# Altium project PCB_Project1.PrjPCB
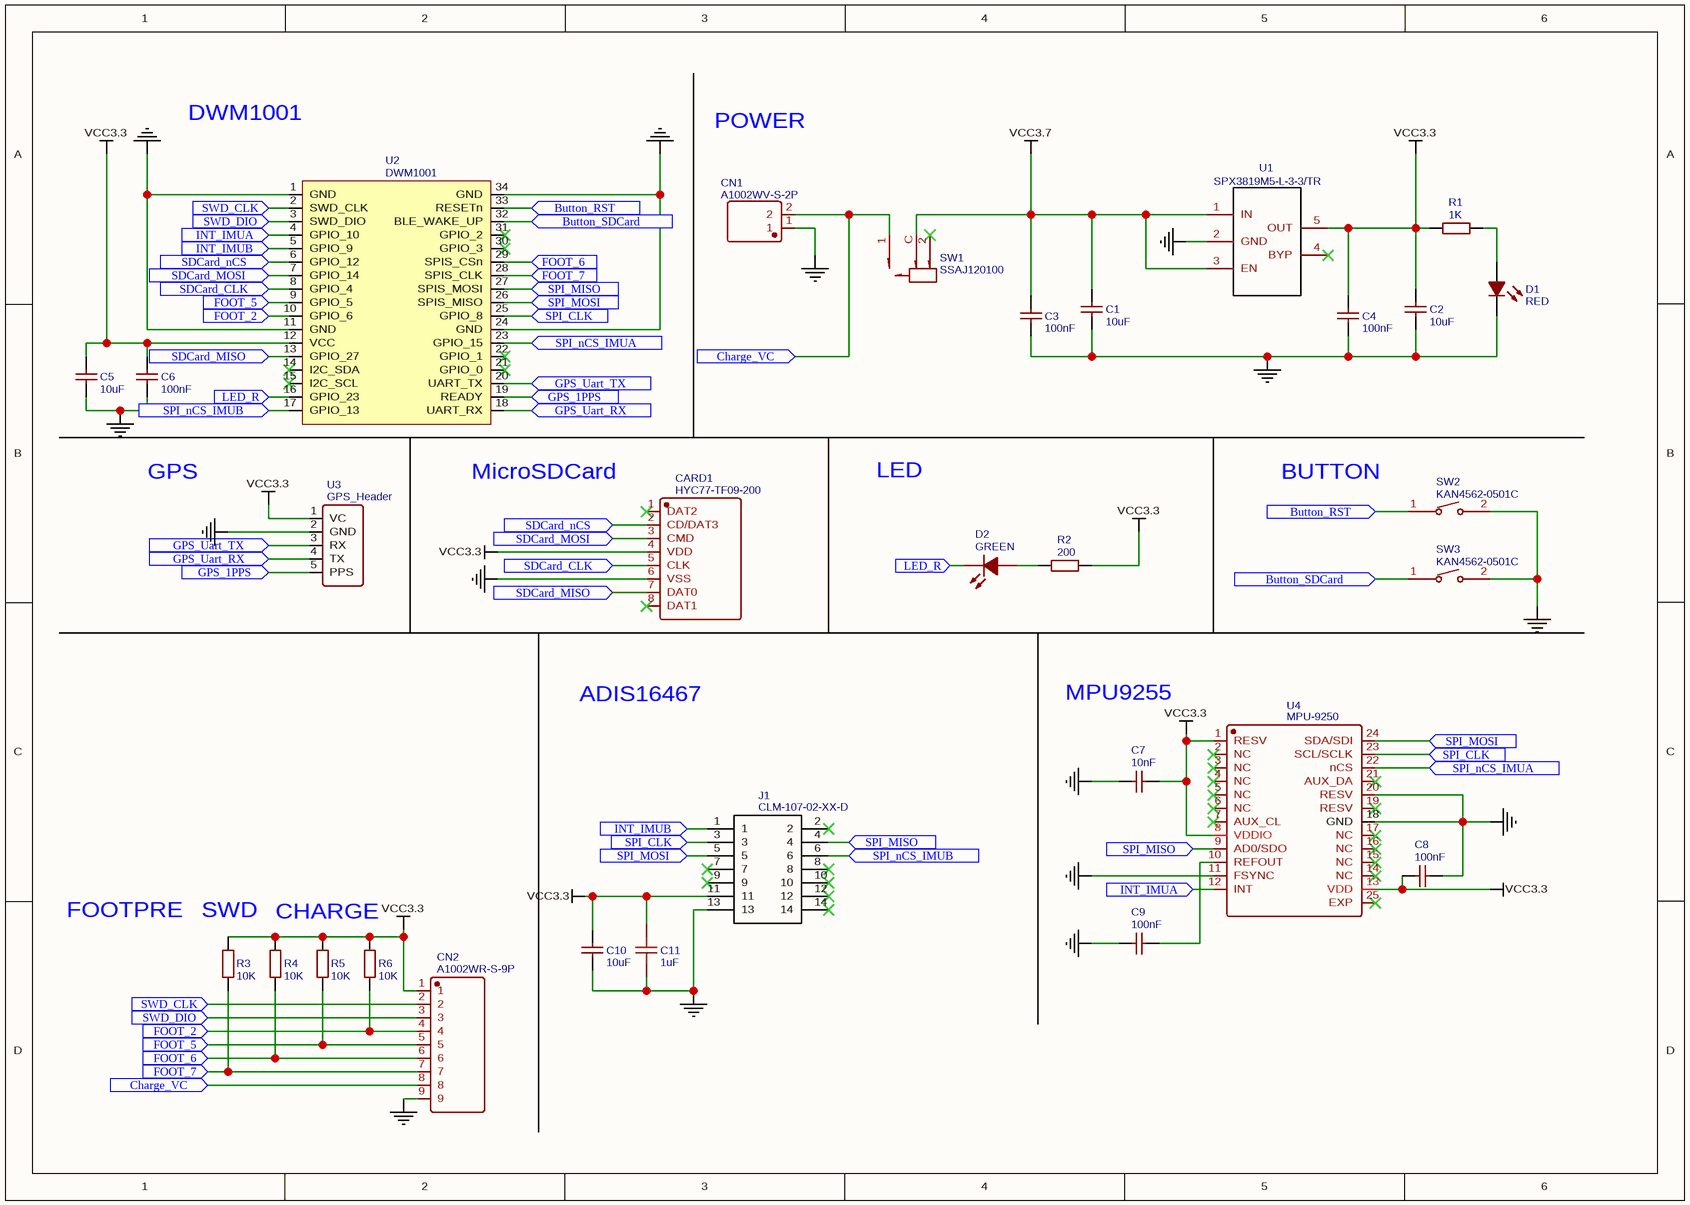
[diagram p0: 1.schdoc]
1 sheet, 30 parts. Net scope: flat (ports and power ports of the same name join across sheets).
Board file: 1.pcbdoc

## Sheet 1.schdoc
size 316 x 224 mm

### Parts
C1  10uF  [0402]
C2  10uF  [0402]
C3  100nF  [0402]
C4  100nF  [0402]
C5  10uF  [0402]
C6  100nF  [0402]
C7  10nF  [0402]
C8  100nF  [0402]
C9  100nF  [0402]
C10  10uF  [0402]
C11  1uF  [0402]
CARD1  HYC77-TF09-200  [TF-015]
CN1  A1002WV-S-2P  [A1002WR-S-2P_LEO]
CN2  A1002WR-S-9P  [A1002WR-S-9P_LEO]
D1  RED  [LED-0603]
D2  GREEN  [LED-0603]
J1  CLM-107-02-XX-D  [*CLM-107-02-XX-D_2]
R1  1K  [0402]
R2  200  [0402]
R3  10K  [0402]
R4  10K  [0402]
R5  10K  [0402]
R6  10K  [0402]
SW1  SSAJ120100  [SW-SMD-5.5X2.5]
SW2  KAN4562-0501C  [KAN4562-0501C]
SW3  KAN4562-0501C  [KAN4562-0501C]
U1  SPX3819M5-L-3-3/TR  [SOT-23-5]
U2  DWM1001  [DWM1001]
U3  GPS_Header  [GPS_HEADER_SMT_NEW]
U4  MPU-9250  [QFN-24-1EP_3X3MM_PITCH0.4MM]

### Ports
Button_RST, Button_SDCard, Charge_VC, FOOT_2, FOOT_5, FOOT_6, FOOT_7, GPS_1PPS, GPS_Uart_RX, GPS_Uart_TX, INT_IMUA, INT_IMUB, LED_R, SDCard_CLK, SDCard_MISO, SDCard_MOSI, SDCard_nCS, SPI_CLK, SPI_MISO, SPI_MOSI, SPI_nCS_IMUA, SPI_nCS_IMUB, SWD_CLK, SWD_DIO

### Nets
GND: C1.1 C2.1 C3.1 C4.1 C5.1 C6.1 C7.1 C8.1 C9.2 C10.1 CARD1.6(VSS) CN1.1 CN2.9 D1.2(C) J1.6 J1.13 SW2.2 SW3.2 U1.2(GND) U2.1(GND) U2.11(GND) U2.17(GPIO_13) U2.24(GND) U2.34(GND) U3.2(GND) U4.11(FSYNC) U4.18(GND) U4.20(RESV) ; port SPI_nCS_IMUB
VCC3.3: C2.2 C4.2 C5.2 C6.2 C7.2 C8.2 C10.2 CARD1.4(VDD) CN2.1 J1.11 R1.1 R2.2 R3.2 R4.2 R5.2 R6.2 U1.5(OUT) U2.12(VCC) U3.1(VC) U4.1(RESV) U4.8(VDDIO) U4.13(VDD)
VCC3.7: C1.2 C3.2 SW1.C U1.1(IN) U1.3(EN)
NetC9_1: C9.1 U4.10(REFOUT)
NetCARD1_2: CARD1.2(CD/DAT3) U2.6(GPIO_12) ; port SDCard_nCS
NetCARD1_3: CARD1.3(CMD) U2.7(GPIO_14) ; port SDCard_MOSI
NetCARD1_5: CARD1.5(CLK) U2.8(GPIO_4) ; port SDCard_CLK
NetCARD1_7: CARD1.7(DAT0) U2.13(GPIO_27) ; port SDCard_MISO
NetCN1_2: CN1.2 CN2.8 SW1.1 ; port Charge_VC
NetCN2_2: CN2.2 CN2.4 CN2.6 R4.1 R6.1 U2.2(SWD_CLK) U2.10(GPIO_6) U2.29(SPIS_CSn) ; port SWD_CLK, port FOOT_2, port FOOT_6
NetCN2_3: CN2.3 CN2.5 CN2.7 R3.1 R5.1 U2.3(SWD_DIO) U2.9(GPIO_5) U2.28(SPIS_CLK) ; port SWD_DIO, port FOOT_5, port FOOT_7
NetD1_1: D1.1(A) R1.2
NetD2_1: D2.1(A) R2.1
NetD2_2: D2.2(K) U2.16(GPIO_23) ; port LED_R
NetJ1_1: J1.1 U2.5(GPIO_9) ; port INT_IMUB
NetJ1_3: J1.3 U2.25(GPIO_8) U4.23(SCL/SCLK) ; port SPI_CLK
NetJ1_4: J1.4 U2.27(SPIS_MOSI) U4.9(AD0/SDO) ; port SPI_MISO
NetJ1_5: J1.5 U2.26(SPIS_MISO) U4.24(SDA/SDI) ; port SPI_MOSI
NetSW2_1: SW2.1 U2.33(RESETn) ; port Button_RST
NetSW3_1: SW3.1 U2.32(BLE_WAKE_UP) ; port Button_SDCard
NetU2_4: U2.4(GPIO_10) U4.12(INT) ; port INT_IMUA
NetU2_18: U2.18(UART_RX) U3.4(TX) ; port GPS_Uart_RX
NetU2_19: U2.19(READY) U3.5(PPS) ; port GPS_1PPS
NetU2_20: U2.20(UART_TX) U3.3(RX) ; port GPS_Uart_TX
NetU2_23: U2.23(GPIO_15) U4.22(nCS) ; port SPI_nCS_IMUA

Not connected (* = marked no-connect by the designer): C11 1 2; CARD1 1(DAT2)* 8(DAT1)*; J1 2* 7* 8* 9* 10* 12* 14*; SW1 2*; U1 4(BYP)*; U2 14(I2C_SDA)* 15(I2C_SCL)* 21(GPIO_0)* 22(GPIO_1)* 30(GPIO_3)* 31(GPIO_2)*; U4 2(NC)* 3(NC)* 4(NC)* 5(NC)* 6(NC)* 7(AUX_CL)* 14(NC)* 15(NC)* 16(NC)* 17(NC)* 19(RESV)* 21(AUX_DA)* 25(EXP)*

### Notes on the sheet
- DWM1001
- POWER
- GPS
- MicroSDCard
- LED
- BUTTON
- ADIS16467
- MPU9255
- FOOTPRE
- (near R3) SWD
- CHARGE

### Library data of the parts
C1 C2 C5 C10 = 10uF: BOM_Manufacturer Part: CL05A106MQ5NUNC; BOM_Manufacturer: SAMSUNG; nameAlias: Capacitance
C3 C4 C6 C8 C9 = 100nF: BOM_Manufacturer Part: CL05B104KO5NNNC; BOM_Manufacturer: SAMSUNG; nameAlias: Capacitance
C7 = 10nF: BOM_Manufacturer Part: CL05B103KB5NNNC; BOM_Manufacturer: SAMSUNG; nameAlias: Capacitance
C11 = 1uF: BOM_Manufacturer: SAMSUNG; BOM_Manufacturer Part: CL05A105KA5NQNC; nameAlias: Capacitance
CARD1 = HYC77-TF09-200: BOM_Manufacturer: 华宇创; Contributor: LCSC
CN1 = A1002WV-S-2P: BOM_Manufacturer: Changjiang Connectors; BOM_Manufacturer Part: A1002WR-S-2P; Contributor: LCSC
CN2 = A1002WR-S-9P: BOM_Manufacturer: Changjiang Connectors; Contributor: LCSC
D1 = RED: BOM_Manufacturer: EVERLIGHT; BOM_Manufacturer Part: 19-213/Y2C-CQ2R2L/3T(CY)
D2 = GREEN: BOM_Manufacturer: KENTO; BOM_Manufacturer Part: KT-0603R
J1 = CLM-107-02-XX-D: Contributor: wangcbYY
R1 = 1K: BOM_Manufacturer: UniOhm; BOM_Manufacturer Part: 0402WGF1001TCE; nameAlias: Resistance (Ohms)
R2 = 200: BOM_Manufacturer: UniOhm; BOM_Manufacturer Part: 0402WGF2000TCE; nameAlias: Resistance (Ohms)
R3-R6 = 10K: BOM_Manufacturer: UniOhm; BOM_Manufacturer Part: 0402WGF1002TCE; nameAlias: Resistance (Ohms)
SW1 = SSAJ120100: BOM_Manufacturer: ALPS Electric; Contributor: LCSC
SW2 SW3 = KAN4562-0501C: BOM_Manufacturer: GANGYUAN; Contributor: LCSC
U1 = SPX3819M5-L-3-3/TR: BOM_Manufacturer: EXAR
U2 = DWM1001: Contributor: wangcbYY
U3 = GPS_Header: Contributor: wangcbYY
U4 = MPU-9250: BOM_Manufacturer: InvenSense; Contributor: LCSC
